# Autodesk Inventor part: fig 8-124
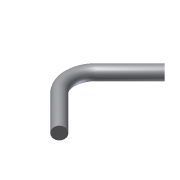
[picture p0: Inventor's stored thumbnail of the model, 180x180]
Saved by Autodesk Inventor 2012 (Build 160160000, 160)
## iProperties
Created: 2007-02
Part Number: fig 8-124
Document SubType Name: Modeling
Designer: Administrator
Density: 1 g/cm^3
Material: Default
Author: Administrator
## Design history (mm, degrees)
node "Sketch1"
sketch "Sketch2"
  geometry: C1 r 5 at (0, 0); 1 further point
  constraints: 1 centre point, 1 coincident, 1 other
  dimensions: "d0" = 10 diameter of C1
extrude "Extrusion1" new body sketch "Sketch2" stored distance "d1" = 100; taper "d2" = 0 deg
workplane "Work Plane1"
sketch "Sketch3"
  geometry: L1 (0, 11)-(0, -8)
  constraints: 2 end point, 1 vertical
feature "Bend Part2" sketch "Sketch3" dims "d5" = 15, "d6" = 90 deg
body "Solid1"
